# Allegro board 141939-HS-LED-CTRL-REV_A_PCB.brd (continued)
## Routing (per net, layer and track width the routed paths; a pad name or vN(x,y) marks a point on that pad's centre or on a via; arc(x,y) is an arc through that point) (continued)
GND_EARTH:
  vias: v1(4.96,54.2) v1(4.96,52.93) v1(4.96,51.66) v1(6.48,54.2)
VCC_5V: length 3.2
  TOP w0.381: v1(18.55,50.9) 18.55,48.99 19.02,48.52 R1.2
  vias: v1(18.55,53.44) v1(18.55,52.17) v1(19.82,53.44) v1(19.82,52.17) v1(24.77,50.01) v1(24.77,49.12) v1(25.66,50.01) v1(25.66,49.12) v1(26.67,50.01) v1(26.67,49.12)
VDDIO_A_RGMII: length 21
  TOP w0.178: U8.27 47.25,33.66 v1(47.41,33.5)
  TOP w0.381: R96.1 R103.1 v1(45.21,31.72) ; R91.1 v1(56.3,33.12)
  BOTTOM w0.381: v1(47.41,33.5) 46.99,33.91 46.99,34.42 47.34,34.77 C44.1 R120.1 ; v1(47.41,33.5) 46.45,33.5 45.21,32.26 v1(45.21,31.72) ; v1(47.41,33.5) 47.95,34.04 55.38,34.04 v1(56.3,33.12)
VDDIO_B_RGMII: length 27
  TOP w0.178: v1(47.41,15.97) 47.25,16.13 U9.27
  TOP w0.381: R98.1 R104.1 v1(46.14,13.46) 46.26,13.34 v1(47.88,13.34) ; R93.1 v1(56.81,16.61)
  BOTTOM w0.381: v1(46.14,13.46) 46.14,12.41 47.12,11.43 49.66,11.43 51.94,13.72 53.98,13.72 54.86,14.61 54.86,14.67 v1(56.81,16.61) ; R122.1 C46.1 47.63,17.11 47.63,16.19 v1(47.41,15.97) 47.78,15.97 48.26,15.49 48.26,13.72 v1(47.88,13.34)
AB16: length 33.1
  TOP w0.152: U26.58 106.85,12.27 105.44,10.87 101.15,10.87 97.1,14.92 85.41,14.92 83.82,16.51 83.82,17.65 83.28,18.19 82.87,18.19 82.41,18.65 82.41,19.57 82.41,19.57 P1.A10
AB17: length 35.6
  TOP w0.152: U26.59 107.35,12.07 105.8,10.51 101,10.51 97.06,14.45 85.22,14.45 81.89,17.78 81.89,21.68 P1.B11
AB18: length 35.9
  TOP w0.152: U26.60 107.85,11.95 106.03,10.13 96.06,10.13 93.01,13.18 85.77,13.18 81.41,17.54 P1.A11
AB19: length 34.3
  TOP w0.152: U26.2 114.85,26.17 111.76,23.08 105.54,23.08 v1(105.41,23.21) ; P1.F3 v1(88.91,25.66)
  BOTTOM w0.152: v1(105.41,23.21) 104.78,22.58 103.26,22.58 101.99,21.31 93.22,21.31 91.1,23.43 90.44,23.43 89.41,24.46 89.41,25.16 v1(88.91,25.66)
ARM_CLK: length 27.3
  TOP w0.152: v1(104.27,23.21) 104.91,23.85 108.72,23.85 109.85,24.98 U26.12 ; P1.D3 89.91,23.66 92.26,23.66 v1(92.71,23.21)
  BOTTOM w0.152: v1(92.71,23.21) 94.24,21.69 101.86,21.69 103.13,22.96 104.02,22.96 v1(104.27,23.21)
AS_DAT0: length 12.4
  TOP w0.152: R13.1 95.01,34.65 94.37,34.01 94.37,31.21 91.83,28.67 90.92,28.67 P1.H2
ASDO: length 22
  TOP w0.152: U7.5 104.15,33.12 101.79,30.77 101.79,29.24 100.46,27.91 100.46,24.48 99.06,23.08 96.4,23.08 95.89,22.58 92,22.58 P1.C1
CAN_RX: length 104.8
  TOP w0.152: v1(30.48,3.56) 30.61,3.68 41.43,3.68 43.59,1.52 104.91,1.52 107.7,4.32 107.7,7.72 112.85,12.87 U26.70
  BOTTOM w0.152: J6.5 20.44,4.19 29.84,4.19 v1(30.48,3.56)
CAN_TX: length 109.8
  TOP w0.152: v1(30.48,2.41) 42.16,2.41 43.43,1.14 105.06,1.14 108.21,4.29 108.21,7.59 113.35,12.73 U26.71
  BOTTOM w0.152: J6.4 18.95,4.7 30.35,4.7 31.11,3.94 31.11,3.05 v1(30.48,2.41)
CLK_25M: length 5.6
  TOP w0.152: X4.3 95.64,26.65 94.16,25.16 P1.E1
CONF_DONE: length 12.4
  TOP w0.152: v1(68.09,25.89) 68.6,25.89 69.76,27.05 74.33,27.05 74.76,27.48 76.03,27.48 76.2,27.66 77.73,27.66 78.24,28.16 P1.H14
  BOTTOM w0.152: R18.1 67.84,25.89 v1(68.09,25.89)
DB0: length 38.6
  TOP w0.152: P1.B12 80.89,21.68 80.89,17.51 85.6,12.8 92.84,12.8 95.9,9.74 106.35,9.74 108.35,11.74 U26.61
DB1: length 39
  TOP w0.152: P1.A12 80.41,17.23 85.22,12.42 92.46,12.42 95.64,9.24 106.56,9.24 108.85,11.53 U26.62
DB2: length 38.2
  TOP w0.152: U26.81 116.08,18.19 115.58,17.69 111.7,17.69 109.1,15.08 103,15.08 102.49,14.57 100.23,14.57 98.07,16.73 87.66,16.73 85.91,18.48 85.91,21.66 P1.B7
DB3: length 36.3
  TOP w0.152: U26.82 115.83,18.69 115.24,18.1 111.41,18.1 108.77,15.46 102.87,15.46 102.47,15.06 100.38,15.06 98.22,17.22 87.71,17.22 86.41,18.52 P1.A6
DB4: length 10.4
  TOP w0.152: U26.38 94.52,21.69 94.05,22.16 P1.B1
DB5: length 11.6
  TOP w0.152: U26.39 92.58,21.19 92.13,21.64 90.88,21.64 P1.A2
DB6: length 13.7
  TOP w0.152: U26.40 94.89,20.69 94.36,20.16 90.56,20.16 89.89,20.83 89.89,21.68 P1.B3
DB7: length 13.2
  TOP w0.152: U26.41 95.02,20.19 94.64,19.8 90.28,19.8 89.41,20.67 P1.A3
DB8: length 15
  TOP w0.152: P1.B4 88.89,21.68 88.89,20.69 90.16,19.42 94.76,19.42 95.03,19.69 U26.42
DB9: length 14.6
  TOP w0.152: P1.A4 88.41,20.4 89.79,19.02 95,19.02 95.17,19.19 U26.43
DB10: length 16.9
  TOP w0.152: P1.B5 87.91,21.66 87.91,19.63 88.9,18.64 100.46,18.64 100.51,18.69 U26.44
DB11: length 16.6
  TOP w0.152: P1.A5 87.41,19.12 88.34,18.19 U26.45
DB12: length 18.8
  TOP w0.152: P1.B6 86.91,21.66 86.91,18.73 87.95,17.69 U26.46
DB13: length 26.7
  TOP w0.152: U26.55 105.35,12.9 104.56,12.1 101.94,12.1 97.69,16.35 87.41,16.35 85.41,18.35 P1.A7
DB14: length 30.4
  TOP w0.152: U26.56 105.85,12.69 104.89,11.73 101.55,11.73 97.37,15.92 87.33,15.92 84.91,18.34 84.91,22.66 P1.C8
DB15: length 32.4
  TOP w0.152: U26.57 106.35,12.48 105.14,11.27 101.38,11.27 97.23,15.42 85.68,15.42 84.2,16.89 84.2,17.88 83.92,18.16 83.92,19.89 82.89,20.92 82.89,21.68 P1.B10
DCLK: length 18.6
  TOP w0.152: U7.6 104.53,34.39 102.62,32.48 99.06,32.48 98.39,33.15 95.25,33.15 94.82,32.72 94.82,31.16 91.82,28.16 P1.H1
ENET_AVDD_3.3: length 32
  TOP w0.178: v2(40.93,38.44) 41.95,38.44 42.17,38.67 U8.14 ; U9.14 40.58,21.14 v2(39.88,21.85)
  BOTTOM w0.381: v2(39.88,21.85) 39.88,26.13 40.14,26.39 40.14,32.13 39.79,32.48 39.79,37.05 40.93,38.2 v2(40.93,38.44) 40.79,38.58 40.68,38.58 39.41,39.85 C59.1 38.39,41.12 C60.1 38.42,42.04 FB3.2
ENET_DVDD_3.3: length 113.3
  TOP w0.178: v2(47.87,41.88) 47.65,41.65 U8.3 ; v2(47.87,24.35) 47.65,24.13 U9.3
  TOP w0.381: v1(42.17,23.97) 41.53,23.97 v1(40.64,24.86) ; R148.1 v1(14.1,12.54) ; R149.1 v1(17.53,12.54) ; R146.1 v1(17.15,48.99) ; R147.1 v1(14.1,48.99)
  BOTTOM w0.381: 15.15,48.99 15.15,47.85 16.29,46.71 28.1,46.71 28.87,47.47 39.15,47.47 40.04,46.58 R94.2 40.04,44.07 FB3.1 40.46,43.66 C58.1 ; 15.15,48.99 v1(17.15,48.99) ; 15.15,48.99 v1(14.1,48.99) ; C58.1 42.07,43.53 42.07,38.2 40.37,36.49 40.37,33.04 40.77,32.64 40.77,24.99 v1(40.64,24.86) 40.64,19.88 39.03,18.26 39.03,14.19 37.37,12.54 v1(17.53,12.54) v1(14.1,12.54) ; C58.1 45.25,43.66 46.26,42.64 C57.1 47.03,42.39 47.53,41.88 v2(47.87,41.88) ; v2(47.87,24.35) 47.11,25.12 44.96,25.12 44.71,24.86 43.06,24.86 v1(42.17,23.97)
ENETA_AVDD_1.1: length 21.7
  TOP w0.178: v2(42.84,37.18) 43.11,37.18 43.4,37.47 U8.17 ; v2(46.29,42.01) 46.45,41.85 U8.6 ; U8.11 43.72,39.87 43.47,40.12 v2(43.47,40.53)
  TOP w0.381: FB1.2 v1(48.8,46.58)
  BOTTOM w0.381: C51.1 43.34,36.67 v2(42.84,37.18) 43.6,37.94 C48.1 43.6,40.38 43.47,40.51 ; 43.47,40.51 44.21,41.24 C47.1 ; 43.47,40.51 v2(43.47,40.53) ; v2(46.29,42.01) 46.39,41.91 C47.1 ; C47.1 48.17,41.24 48.8,41.88 v1(48.8,46.58)
ENETA_DVDD_1.1: length 10.3
  TOP w0.178: v1(50.2,39.34) 49.93,39.07 U8.38
  TOP w0.381: FB1.1 C50.1 C49.1 51.6,43.02 L6.1 50.62,42.04 v1(50.2,41.63)
  BOTTOM w0.381: v1(50.2,41.63) v1(50.2,39.34)
ENETA_DVDD_2.5: length 61.9
  TOP w0.178: U8.8 45.65,41.3 45.25,41.7 v2(45.25,41.88)
  TOP w0.381: R125.1 v1(41.06,35.1) ; R124.1 v1(54.14,40.61) ; v1(42.2,29.48) 42.63,29.48 42.96,29.81 R100.1 ; R123.1 v1(54.14,39.34) ; R126.1 v1(54.14,41.88)
  BOTTOM w0.381: v1(54.14,41.88) v1(54.14,40.61) v1(54.14,39.34) ; v1(54.14,39.34) 54.14,39.09 52.36,37.31 C43.1 48.8,35.83 R120.2 ; v1(54.14,39.34) 55.5,37.98 55.5,35.56 56.39,34.67 58.04,34.67 59.18,33.53 59.18,32 56.77,29.59 50.29,29.59 49.02,30.86 46.48,30.86 45.97,30.35 43.69,30.35 42.82,29.48 v1(42.2,29.48) 41.48,30.21 41.48,34.09 41.06,34.51 v1(41.06,35.1) 41.06,36.29 42.71,37.94 42.71,40.86 43.72,41.88 v2(45.25,41.88)
ENETA_GTX_CLK: length 24.2
  TOP w0.152: R39.1 56.68,35.4 57.47,34.61 62.07,34.61 62.38,34.92 62.68,34.92 62.99,34.61 63.28,34.61 63.88,34.01 71.71,34.01 v1(71.84,33.88) ; P1.P14 v1(77.91,33.66)
  BOTTOM w0.152: v1(77.91,33.66) 77.72,33.85 71.86,33.85 v1(71.84,33.88)
ENETA_INTN: length 46
  TOP w0.152: v1(79.91,30.66) 80.41,30.16 P1.K12 ; R125.2 43.8,35.1 v2(43.85,35.15) 43.85,36.14 43.98,36.27 U8.20 ; v1(58.17,33.53) 58.17,33.58 58.37,33.78 62.87,33.78 63.66,32.99 71.05,32.99 71.28,32.77 v1(71.28,32.2)
  BOTTOM w0.152: v1(79.91,30.66) 79.41,31.16 78.69,31.16 78.49,31.37 78.49,31.38 78.41,31.46 78.41,31.95 77.98,32.38 73.53,32.38 73.46,32.46 73.46,32.46 73.13,32.79 72.54,32.79 71.96,32.2 v1(71.28,32.2) ; v2(43.85,35.15) 43.85,34.48 44.32,34.01 44.32,31.75 44.96,31.11 45.97,31.11 46.48,31.62 56.26,31.62 v1(58.17,33.53)
ENETA_LED_1000: length 7.2
  TOP w0.152: R56.1 R100.2 R76.2 44.3,31.51 44.3,34.2 44.74,34.64 44.87,34.64 45.25,35.02 U8.22
ENETA_LED_ACT: length 4.5
  TOP w0.152: R51.1 R90.2 R73.2 44.49,35.02 44.49,35.02 44.84,35.38 U8.21
ENETA_MDC: length 30.7
  TOP w0.152: U8.40 49.33,39.87 50.07,40.61 R124.2 52.23,41.12 52.36,41.24 55.03,41.24 58.93,37.34 72.36,37.34 74.54,35.16 P1.R16
ENETA_MDI_N0: length 9.8
  TOP w0.13: U8.10 44.84,40.86 44.88,40.9 44.88,41.02 44.6,41.29 43.07,41.29 42.92,41.14 42.92,41.02 42.77,40.86 42.55,40.86 42.4,41.02 42.4,41.14 42.25,41.29 40.57,41.29 39.84,40.57 38.14,40.57 37.8,40.23 U23.23
ENETA_MDI_N1: length 8.3
  TOP w0.13: U23.20 37.8,37.18 38.14,37.52 38.48,37.52 40.06,39.1 43.53,39.1 43.56,39.07 U8.13
ENETA_MDI_N2: length 9.4
  TOP w0.13: U23.17 37.76,34.13 38.1,34.47 38.57,34.47 39.03,34.93 39.03,35.53 40.93,37.43 42.29,37.43 42.76,37.9 43.82,37.9 43.85,37.87 U8.16
ENETA_MDI_N3: length 11.1
  TOP w0.13: U23.14 37.8,31.08 38.14,31.43 38.48,31.43 40.3,33.24 40.3,35.31 41.27,36.29 43.24,36.29 43.65,36.7 43.82,36.7 43.85,36.67 U8.19
ENETA_MDI_P0: length 9.8
  TOP w0.13: U23.24 37.8,41.24 38.14,40.9 39.7,40.9 40.43,41.63 44.74,41.63 45.21,41.15 45.21,40.9 45.25,40.86 U8.9
ENETA_MDI_P1: length 8.3
  TOP w0.13: U23.21 37.8,38.2 38.14,37.86 38.34,37.86 39.92,39.44 43.53,39.44 43.56,39.47 U8.12
ENETA_MDI_P2: length 9.4
  TOP w0.13: U8.15 43.85,38.27 43.82,38.24 42.62,38.24 42.15,37.77 40.79,37.77 38.69,35.67 38.69,35.07 38.43,34.81 38.1,34.81 37.76,35.15 U23.18
ENETA_MDI_P3: length 11.1
  TOP w0.13: U23.15 37.8,32.1 38.14,31.76 38.34,31.76 39.96,33.38 39.96,35.45 41.14,36.62 43.1,36.62 43.52,37.04 43.85,37.04 43.88,37.07 U8.18
ENETA_MDIO: length 31.7
  TOP w0.152: P1.P15 76.93,34.64 74.43,34.64 72.11,36.96 58.43,36.96 55.41,39.97 52.49,39.97 52.23,39.72 R123.2 51.6,39.34 50.96,39.97 50.02,39.97 49.52,39.47 U8.39
ENETA_RESETN: length 32.9
  TOP w0.152: U8.1 48.45,40.76 48.68,40.99 50.96,40.99 51.85,41.88 R126.2 52.23,42.39 52.36,42.51 54.32,42.51 59.11,37.72 72.74,37.72 73.28,37.18 76.39,37.18 P1.T15
ENETA_RX_CLK: length 35.6
  TOP w0.152: P1.M15 77.41,31.85 77.21,31.64 76.15,31.64 75.54,32.26 73.79,32.26 73.2,31.67 72.44,31.67 72.26,31.85 72.26,32.4 72.15,32.51 71.99,32.51 71.88,32.4 71.88,31.83 71.68,31.62 70.82,31.62 70.61,31.83 70.61,32.35 70.45,32.51 70.22,32.51 70.06,32.35 70.06,31.8 69.88,31.62 69.62,31.62 69.45,31.8 69.45,32.33 69.27,32.51 69.02,32.51 68.84,32.33 68.84,31.8 68.66,31.62 68.41,31.62 68.23,31.8 68.23,32.35 68.07,32.51 67.85,32.51 67.69,32.35 67.69,31.8 67.51,31.62 67.26,31.62 67.08,31.8 67.08,32.43 66.9,32.61 66.65,32.61 66.47,32.43 66.47,31.93 66.29,31.75 66.04,31.75 65.86,31.93 65.86,32.43 65.68,32.61 63.96,32.61 63.75,32.41 63.75,32.28 63.61,32.13 63.39,32.13 63.25,32.28 63.25,32.87 63.1,33.02 62.89,33.02 62.74,32.87 62.74,32.02 62.59,31.88 62.38,31.88 62.24,32.02 62.24,33.1 62.06,33.27 58.75,33.27 58.55,33.07 58.55,32.97 58.34,32.77 56.98,32.77 56.69,32.48 54.55,32.48 54.35,32.68 R121.1
ENETA_RX_D0: length 33.2
  TOP w0.152: P1.L15 76.92,30.68 76.1,30.68 75.57,31.21 73.79,31.21 73.52,30.95 72.98,30.95 72.78,30.75 65.91,30.75 65.66,31.01 63.37,31.01 63.35,30.99 63.23,30.99 63.05,30.81 63.05,30.4 62.87,30.23 62.62,30.23 62.44,30.4 62.44,30.81 62.26,30.99 62.01,30.99 61.83,30.81 61.83,30.4 61.65,30.23 61.4,30.23 61.22,30.4 61.22,30.8 61.04,30.99 60.78,30.99 60.59,30.8 60.59,30.11 60.3,29.81 60.09,29.81 59.91,29.99 59.91,30.81 59.73,30.99 59.48,30.99 59.3,30.81 59.3,29.99 59.12,29.81 58.87,29.81 58.69,29.99 58.69,30.81 58.51,30.99 58.26,30.99 58.08,30.81 58.08,29.99 57.9,29.81 57.65,29.81 57.47,29.99 57.47,30.81 57.29,30.99 57.04,30.99 56.86,30.81 56.86,29.99 56.68,29.81 54.48,29.81 54.35,29.95 R27.1
ENETA_RX_D1: length 34.5
  TOP w0.152: v1(73.54,30.39) 73.43,30.28 65.86,30.28 65.51,30.63 63.88,30.63 63.62,30.36 63.62,29.96 63.5,29.84 60.83,29.84 60.42,29.43 60.1,29.43 59.92,29.26 59.92,29.01 59.75,28.83 59.49,28.83 59.31,29.01 59.31,29.26 59.14,29.43 58.88,29.43 58.7,29.26 58.7,29.01 58.53,28.83 58.27,28.83 58.1,29.01 58.1,29.26 57.92,29.43 57.66,29.43 57.49,29.26 57.49,29.01 57.31,28.83 57.05,28.83 56.88,29.01 56.88,29.26 56.7,29.43 56.45,29.43 56.27,29.26 56.27,29.01 56.1,28.83 55.84,28.83 55.66,29.01 55.66,29.26 55.49,29.43 55.23,29.43 55.06,29.26 55.06,29.01 54.88,28.83 54.62,28.83 54.45,29.01 54.45,29.26 54.27,29.43 53.47,29.43 53,29.91 R30.1 ; P1.J12 80.41,29.16 v1(79.91,29.66)
  BOTTOM w0.152: v1(79.91,29.66) 79.41,30.16 78.61,30.16 78.38,30.39 78.38,30.96 78.18,31.16 74.31,31.16 v1(73.54,30.39)
ENETA_RX_D2: length 34.9
  TOP w0.152: v1(73.54,29.26) 72.9,29.89 68.16,29.89 67.49,29.23 63.81,29.23 63.58,29 63.58,28.66 63.34,28.42 63.04,28.42 62.86,28.6 62.86,29.29 62.68,29.46 62.43,29.46 62.25,29.29 62.25,28.6 62.07,28.42 61.82,28.42 61.64,28.6 61.64,29.29 61.46,29.46 61.21,29.46 61.03,29.29 61.03,28.6 60.85,28.42 53.88,28.42 52.61,29.69 50.58,29.69 R35.1 ; v1(77.91,29.66) 78.41,29.16 P1.J14
  BOTTOM w0.152: v1(77.91,29.66) 74.37,29.66 73.96,29.26 v1(73.54,29.26)
ENETA_RX_D3: length 39
  TOP w0.152: v1(78.91,29.66) 79.41,29.16 P1.J13 ; R37.1 44.65,32.52 44.65,31.43 45.47,30.61 48.52,30.61 49.06,30.07 49.62,30.07 50.51,29.18 52.48,29.18 53.62,28.04 67.31,28.04 68.54,29.26 v1(72.65,29.26)
  BOTTOM w0.152: v1(78.91,29.66) 78.67,29.66 78.17,30.16 74.28,30.16 73.94,29.82 73.21,29.82 v1(72.65,29.26)
ENETA_RX_DV: length 36.2
  TOP w0.152: P1.L16 76.13,31.16 75.57,31.72 73.76,31.72 73.34,31.3 72.61,31.3 72.52,31.21 65.99,31.21 65.79,31.41 62.01,31.41 61.83,31.59 61.83,32.71 61.65,32.89 61.4,32.89 61.22,32.71 61.22,31.54 61.05,31.37 60.8,31.37 60.62,31.54 60.62,32.71 60.44,32.89 60.19,32.89 60.01,32.71 60.01,31.51 59.87,31.37 59.67,31.37 59.53,31.51 59.53,32.71 59.35,32.89 59.09,32.89 58.92,32.71 58.92,31.52 58.77,31.37 58.56,31.37 58.41,31.52 58.41,32.21 58.23,32.38 57.98,32.38 57.8,32.21 57.8,31.55 57.62,31.37 57.37,31.37 57.19,31.55 57.19,31.83 57.01,32 56.76,32 56.58,31.83 56.58,31.28 56.41,31.11 56.18,31.11 56.01,31.28 56.01,31.88 55.78,32.1 53.92,32.1 53.72,32.3 53.72,33.02 53.62,33.12 R24.1
ENETA_TX_D0: length 27.3
  TOP w0.152: P1.N14 77.88,32.63 73.89,32.63 72.01,34.51 64.52,34.51 64.34,34.69 64.34,34.83 63.86,35.31 57.28,35.31 56.55,36.04 54.01,36.04 53.38,36.67 R43.1
ENETA_TX_D1: length 24.4
  TOP w0.152: R45.1 56.68,36.67 57.67,35.68 64.64,35.68 64.82,35.5 64.82,35.2 65,35.02 65.25,35.02 65.43,35.2 65.43,35.5 65.61,35.68 65.86,35.68 66.04,35.5 66.04,35.2 66.22,35.02 66.47,35.02 66.65,35.2 66.65,35.5 66.83,35.68 67.08,35.68 67.26,35.5 67.26,35.2 67.44,35.02 72.14,35.02 74,33.16 P1.N16
ENETA_TX_D2: length 27.4
  TOP w0.152: R47.1 53.38,37.69 53.63,37.69 54.01,37.31 56.81,37.31 57.92,36.2 67.61,36.2 67.79,36.02 67.79,35.71 67.97,35.53 68.22,35.53 68.4,35.71 68.4,36.02 68.58,36.2 68.83,36.2 69.01,36.02 69.01,35.71 69.19,35.53 72.27,35.53 74.17,33.62 76.95,33.62 P1.N15
ENETA_TX_D3: length 24.5
  TOP w0.152: R49.1 56.68,37.94 58.04,36.58 69.37,36.58 69.54,36.4 69.54,36.06 69.72,35.89 69.97,35.89 70.15,36.06 70.15,36.4 70.33,36.58 70.58,36.58 70.76,36.4 70.76,36.06 70.94,35.89 71.19,35.89 71.37,36.06 71.37,36.4 71.55,36.58 71.86,36.58 74.27,34.16 P1.P16
ENETA_TX_EN: length 27.1
  TOP w0.152: v1(77.91,31.66) 78.41,31.16 P1.L14 ; R41.1 53.4,35.4 54.04,34.77 56.68,34.77 57.28,34.16 63,34.16 63.66,33.5 71.4,33.5 71.63,33.27 72.01,33.27 72.9,32.38 v1(72.9,32.23)
  BOTTOM w0.152: v1(72.9,32.23) 73.47,31.66 v1(77.91,31.66)
ENETB_AVDD_1.1: length 23.5
  TOP w0.178: v2(42.84,22.58) 43.07,22.34 U9.11 ; U9.6 46.45,24.33 v2(46.29,24.48) ; v2(42.84,19.65) 43.11,19.65 43.4,19.94 U9.17
  TOP w0.381: FB2.2 49.95,28.93 v1(49.57,29.31)
  BOTTOM w0.381: v2(46.29,24.48) 46.39,24.38 C54.1 ; C56.1 43.09,22.32 v2(42.84,22.58) ; C56.1 43.6,22.96 43.85,23.21 45.12,23.21 45.63,23.72 C54.1 ; C56.1 43.6,20.42 v2(42.84,19.65) 43.34,19.15 C55.1 ; C54.1 48.39,23.72 49.57,24.89 v1(49.57,29.31)
ENETB_DVDD_1.1: length 10.9
  TOP w0.178: v1(50.2,21.81) 49.93,21.54 U9.38
  TOP w0.381: FB2.1 52.74,27.91 C53.1 C52.1 53,25.75 L7.1 51.51,24.77 50.96,24.23 v1(50.58,24.23)
  BOTTOM w0.381: v1(50.58,24.23) 50.2,23.85 v1(50.2,21.81)
ENETB_DVDD_2.5: length 45.2
  TOP w0.178: U9.8 45.65,23.78 45.25,24.18 v2(45.25,24.35)
  TOP w0.381: R29.1 v1(40.93,17.5) ; R23.1 v1(53.43,21.81) ; R34.1 v1(54.82,24.35) ; R26.1 v1(53.43,23.08) ; R102.1 v1(41.01,14.83)
  BOTTOM w0.381: v1(54.82,24.35) 54.14,24.35 53.43,23.64 v1(53.43,23.08) v1(53.43,21.81) 51.39,19.78 C45.1 48.8,18.3 R122.2 49.28,18.26 49.66,17.88 49.66,12.83 49.4,12.57 47.37,12.57 46.91,13.03 46.91,13.79 45.88,14.83 v1(41.01,14.83) 40.3,15.54 40.3,16.86 v1(40.93,17.5) 40.93,18.26 42.21,19.54 42.21,22.97 43.34,24.1 44.99,24.1 v2(45.25,24.35)
ENETB_GTX_CLK: length 29.1
  TOP w0.152: R40.1 53.63,18.89 54.14,19.4 56.77,19.4 57.95,20.57 59.18,20.57 61.69,23.08 69.1,23.08 70.11,24.1 75.03,24.1 75.57,24.63 76.61,24.63 76.92,24.94 76.92,25.45 77.12,25.65 77.9,25.65 P1.F14
ENETB_INTN: length 53
  TOP w0.152: R29.2 43.68,17.5 v1(43.7,17.52) 43.7,18.47 43.98,18.74 U9.20 ; v1(76.84,17.75) 76.84,15.63 75.56,14.35 59.98,14.35 57.54,11.91 45.22,11.91 44.2,12.92 v1(44.2,15.59) ; P1.C11 v1(80.91,22.66)
  BOTTOM w0.152: v1(44.2,15.59) 44.2,17.02 v1(43.7,17.52) ; v1(76.84,17.75) 77.22,18.13 77.22,20.29 77.47,20.54 80.4,20.54 80.91,21.05 v1(80.91,22.66)
ENETB_LED_1000: length 6
  TOP w0.152: R60.1 R102.2 R89.2 43.47,15.97 44.61,17.11 44.87,17.11 45.25,17.49 U9.22
ENETB_LED_ACT: length 8
  TOP w0.152: R52.1 R92.2 R77.2 40.8,16.61 43.6,16.61 44.49,17.5 44.49,17.5 44.84,17.85 U9.21
ENETB_MDC: length 31.8
  TOP w0.152: U9.40 49.33,22.34 50.07,23.08 R26.2 51.6,23.46 51.85,23.72 55.41,23.72 58.61,26.92 64.55,26.92 64.9,27.27 68.3,27.27 69.22,28.19 73.95,28.19 75.44,29.69 76.93,29.69 P1.K15
ENETB_MDI_N0: length 11.6
  TOP w0.13: U23.11 37.8,28.04 38.14,28.38 38.97,28.38 41.2,26.15 41.2,25.74 43.22,23.72 43.55,23.72 43.7,23.57 43.7,23.45 43.85,23.3 44.06,23.3 44.22,23.45 44.22,23.57 44.37,23.72 44.65,23.72 44.88,23.49 44.88,23.34 44.84,23.3 U9.10
ENETB_MDI_N1: length 9.2
  TOP w0.13: U9.13 43.56,21.54 43.53,21.58 42.31,21.58 38.56,25.33 38.14,25.33 37.8,24.99 U23.8
ENETB_MDI_N2: length 8.5
  TOP w0.13: U23.5 37.29,21.94 37.63,22.28 37.92,22.28 39.83,20.38 43.53,20.38 43.56,20.34 U9.16
ENETB_MDI_N3: length 8
  TOP w0.13: U23.2 37.8,18.89 38.14,19.23 38.47,19.23 38.94,18.77 43.23,18.77 43.64,19.18 43.85,19.18 43.88,19.14 U9.19
ENETB_MDI_P0: length 11.7
  TOP w0.13: U23.12 37.8,29.05 38.14,28.71 39.11,28.71 41.53,26.29 41.53,25.88 43.36,24.05 44.79,24.05 45.21,23.63 45.21,23.34 45.25,23.3 U9.9
ENETB_MDI_P1: length 9.2
  TOP w0.13: U9.12 43.56,21.94 43.53,21.91 42.45,21.91 38.69,25.66 38.14,25.66 37.8,26 U23.9
ENETB_MDI_P2: length 8.5
  TOP w0.13: U23.6 37.29,22.96 37.63,22.62 38.06,22.62 39.96,20.71 43.53,20.71 43.56,20.74 U9.15
ENETB_MDI_P3: length 8
  TOP w0.13: U9.18 43.88,19.54 43.85,19.51 43.5,19.51 43.09,19.1 39.07,19.1 38.6,19.57 38.14,19.57 37.8,19.91 U23.3
ENETB_MDIO: length 31.1
  TOP w0.152: P1.J16 75.43,29.16 74.08,27.81 69.38,27.81 68.48,26.92 65.18,26.92 64.68,26.42 58.61,26.42 55.54,23.34 54.49,23.34 53.6,22.45 51.73,22.45 51.6,22.32 R23.2 51.09,21.81 50.53,22.37 49.92,22.37 49.49,21.94 U9.39
ENETB_RESETN: length 31.3
  TOP w0.152: P1.K16 75.41,30.16 73.82,28.57 68.88,28.57 67.96,27.66 64.77,27.66 64.55,27.43 58.49,27.43 56.04,24.99 53.38,24.99 53,24.61 R34.2 51.85,24.35 51.09,23.59 48.8,23.59 48.45,23.23 U9.1
ENETB_RX_CLK: length 34.6
  TOP w0.152: R22.1 57.33,17.71 57.66,18.03 57.66,18.73 57.85,18.92 58.13,18.92 58.32,18.73 58.32,17.96 58.5,17.78 58.75,17.78 58.93,17.96 58.93,19 59.11,19.18 59.36,19.18 59.54,19 59.54,17.96 59.72,17.78 59.97,17.78 60.15,17.96 60.15,19 60.33,19.18 60.58,19.18 60.76,19 60.76,17.96 60.94,17.78 61.19,17.78 61.37,17.96 61.37,19 61.55,19.18 61.8,19.18 61.98,19 61.98,17.96 62.16,17.78 62.41,17.78 62.59,17.96 62.59,19 62.77,19.18 68.23,19.18 72.01,22.96 75.06,22.96 75.8,23.69 76.69,23.69 76.93,23.94 76.93,24.44 77.41,24.92 P1.E15
ENETB_RX_D0: length 32.4
  TOP w0.152: R28.1 57.12,15.34 58.55,16.76 68.2,16.76 70.02,18.58 70.27,18.58 70.84,18 71.1,18 71.27,18.18 71.27,18.44 70.7,19.01 70.7,19.26 70.88,19.44 71.13,19.44 71.71,18.87 71.96,18.87 72.14,19.05 72.14,19.3 71.56,19.87 71.56,20.13 71.74,20.31 71.99,20.31 72.57,19.73 72.82,19.73 73,19.91 73,20.16 72.42,20.74 72.42,20.99 72.6,21.17 72.86,21.17 73.43,20.59 73.68,20.59 73.86,20.77 73.86,21.02 73.29,21.6 73.29,21.85 73.5,22.07 75.32,22.07 75.92,22.68 76.69,22.68 77.17,23.16 P1.C15
ENETB_RX_D1: length 33.4
  TOP w0.152: R32.1 52.87,13.43 56.93,13.43 57.76,14.26 57.76,14.51 57.53,14.73 57.53,14.99 57.71,15.16 57.96,15.16 58.19,14.94 58.44,14.94 58.62,15.12 58.62,15.37 58.39,15.6 58.39,15.85 58.57,16.03 58.83,16.03 59.05,15.8 59.3,15.8 59.76,16.26 69.85,16.26 70.21,16.61 70.46,16.61 70.83,16.24 71.08,16.24 71.26,16.42 71.26,16.67 70.89,17.04 70.89,17.3 71.07,17.48 71.32,17.48 71.69,17.1 71.95,17.1 72.13,17.28 72.13,17.53 71.75,17.91 71.75,18.16 71.93,18.34 72.18,18.34 72.56,17.97 72.81,17.97 72.99,18.14 72.99,18.4 72.62,18.77 72.62,19.02 75.03,21.43 75.32,21.43 76.05,22.16 P1.B16
ENETB_RX_D2: length 34.5
  TOP w0.152: P1.C14 77.92,22.68 77.19,22.68 76.89,22.37 76.89,21.86 76.71,21.69 76.2,21.69 75.32,20.8 75.03,20.8 73.6,19.37 73.6,18.22 70.99,15.62 59.85,15.62 57.15,12.92 49.82,12.92 R36.1
ENETB_RX_D3: length 38.4
  TOP w0.152: P1.A15 76.46,20.21 76.46,20.04 71.54,15.11 60.11,15.11 57.41,12.42 46.14,12.42 44.99,13.56 R38.1
ENETB_RX_DV: length 36.3
  TOP w0.152: P1.C16 75.78,23.16 75.19,22.58 73.12,22.58 67.94,17.4 67.64,17.4 67.46,17.58 67.46,18.62 67.28,18.8 67.03,18.8 66.85,18.62 66.85,17.58 66.67,17.4 66.42,17.4 66.24,17.58 66.24,18.62 66.06,18.8 65.81,18.8 65.63,18.62 65.63,17.58 65.45,17.4 65.2,17.4 65.02,17.58 65.02,18.62 64.84,18.8 64.59,18.8 64.41,18.62 64.41,17.58 64.24,17.4 63.98,17.4 63.8,17.58 63.8,18.62 63.63,18.8 63.37,18.8 63.19,18.62 63.19,17.58 63.02,17.4 58.58,17.4 57.15,15.97 53.88,15.97 53.76,16.1 R25.1
ENETB_TX_D0: length 26
  TOP w0.152: R44.1 56.52,20.04 58.09,21.61 58.34,21.61 58.58,21.37 58.83,21.37 59.01,21.55 59.01,21.8 58.77,22.04 58.77,22.29 58.95,22.47 59.21,22.47 59.44,22.23 59.7,22.23 59.87,22.41 59.87,22.66 59.64,22.9 59.64,23.15 60.05,23.57 68.86,23.57 70.41,25.12 74.68,25.12 75.26,25.7 76.66,25.7 77.12,26.16 P1.F15
ENETB_TX_D1: length 29.2
  TOP w0.152: R46.1 53.76,20.16 54.27,20.67 56.42,20.67 59.7,23.95 59.94,23.95 60.12,24.13 60.12,24.46 60.3,24.64 60.55,24.64 60.73,24.46 60.73,24.13 60.9,23.95 61.16,23.95 61.34,24.13 61.34,24.46 61.51,24.64 61.77,24.64 61.95,24.46 61.95,24.13 62.12,23.95 62.38,23.95 62.55,24.13 62.55,24.46 62.73,24.64 62.99,24.64 63.16,24.46 63.16,24.13 63.34,23.95 68.52,23.95 70.2,25.63 74.56,25.63 75.09,26.16 P1.F16
ENETB_TX_D2: length 25.3
  TOP w0.152: R48.1 56.61,22.02 56.86,22.02 56.9,21.98 57.15,21.98 57.33,22.15 57.33,22.41 57.29,22.45 57.29,22.7 57.47,22.88 57.72,22.88 57.76,22.84 58.02,22.84 58.2,23.02 58.2,23.27 58.15,23.31 58.15,23.57 59.6,25.02 64.33,25.02 65.02,24.33 68.3,24.33 70.15,26.17 74.46,26.17 74.93,26.64 76.89,26.64 P1.G15
ENETB_TX_D3: length 24.7
  TOP w0.152: P1.G16 74.95,27.16 74.43,26.64 69.98,26.64 68.05,24.71 65.46,24.71 64.52,25.65 58.84,25.65 58.14,24.95 58.14,24.7 58.31,24.53 58.31,24.27 58.13,24.1 57.88,24.1 57.71,24.27 57.45,24.27 57.28,24.09 57.28,23.84 57.45,23.66 57.45,23.41 57.27,23.23 57.02,23.23 56.84,23.4 56.59,23.4 R50.1
ENETB_TX_EN: length 25.1
  TOP w0.152: P1.D16 75.57,24.16 75,23.59 70.24,23.59 69.35,22.7 63.47,22.7 62.34,21.58 62.09,21.58 61.77,21.89 61.52,21.89 61.34,21.72 61.34,21.46 61.66,21.14 61.66,20.89 61.48,20.71 61.23,20.71 60.91,21.03 60.66,21.03 60.48,20.85 60.48,20.6 60.8,20.28 60.8,20.03 60.43,19.67 58.06,19.67 57.2,18.81 R42.1
F_CLK: length 39.4
  TOP w0.152: v1(105.41,18.51) 113.42,18.51 114.59,19.69 U26.84 ; P1.F8 v1(84.91,25.66)
  BOTTOM w0.152: v1(84.91,25.66) 85.41,25.16 85.41,22.27 85.98,21.69 85.98,20.19 88.22,17.95 104.86,17.95 v1(105.41,18.51)
F_NAD: length 33.5
  TOP w0.152: v1(104.27,20.8) 104.83,21.36 112.45,21.36 115.28,24.19 U26.93 ; P1.C3 v1(88.91,23.66)
  BOTTOM w0.152: v1(104.27,20.8) 103.38,20.8 102.75,20.16 89.79,20.16 89.41,20.55 P1.C3 v1(88.91,23.66)
F_NBL0: length 35.2
  TOP w0.152: v1(105.41,21.94) 111.96,21.94 116.21,26.19 U26.97 ; P1.E6 v1(86.91,24.66)
  BOTTOM w0.152: v1(105.41,21.94) 104.86,21.38 103.33,21.38 102.49,20.54 92.32,20.54 90.41,22.46 90.41,22.87 89.12,24.16 87.7,24.16 87.2,24.66 v1(86.91,24.66)
F_NBL1: length 30
  TOP w0.152: P1.C2 v1(90.91,22.66) ; v1(104.27,21.94) 104.83,22.5 111.94,22.5 116.13,26.69 U26.98
  BOTTOM w0.152: v1(104.27,21.94) 103.13,21.94 102.11,20.92 92.65,20.92 v1(90.91,22.66)
F_NCE2: length 33.6
  TOP w0.152: P1.D5 v1(87.91,23.66) ; v1(105.41,20.8) 112.87,20.8 113.76,21.69 U26.88
  BOTTOM w0.152: v1(87.91,23.66) 88.41,23.16 88.41,20.91 89.54,19.78 103,19.78 103.46,20.24 104.86,20.24 v1(105.41,20.8)
F_NWAIT: length 36.5
  TOP w0.152: P1.E7 v1(85.91,24.66) ; v1(104.27,19.65) 104.83,20.21 113,20.21 113.97,21.19 U26.87
  BOTTOM w0.152: v1(85.91,24.66) 86.41,24.16 87.12,24.16 87.41,23.87 87.41,21.15 89.23,19.32 103.26,19.32 103.59,19.65 v1(104.27,19.65)
GPIO: length 32
  TOP w0.152: v1(108.59,27.66) 108.35,27.89 U26.15 ; v1(87.91,28.66) 87.2,28.66 86.88,28.98 86.88,29.68 86.41,30.15 P1.K6
  BOTTOM w0.152: v1(87.91,28.66) 88.41,29.16 89.22,29.16 89.74,29.69 92.46,29.69 93.34,28.8 93.34,26.52 95.76,24.1 100.08,24.1 101.22,25.24 101.22,27.15 101.99,27.91 108.34,27.91 v1(108.59,27.66)
HUB1_A: length 29.6
  TOP w0.152: U29.8 v1(75.32,45.05) ; P1.T6 86.41,37.73 89.76,41.08 U28.7 89.76,45.09 88.27,46.58 75.82,46.58 v1(75.44,46.96)
  BOTTOM w0.152: v1(75.32,45.05) 75.32,46.84 v1(75.44,46.96)
HUB1_B: length 33.7
  TOP w0.152: v1(74.02,46.96) 74.66,47.59 76.71,47.59 77.35,46.96 88.9,46.96 90.41,45.45 U28.8 90.41,40.97 86.91,37.47 86.91,35.66 P1.R6 ; U29.6 v1(74.02,45.05)
  BOTTOM w0.152: v1(74.02,46.96) v1(74.02,45.05)
HUB1_B1: length 32.4
  TOP w0.152: v1(98.94,46.32) 98.94,46.2 97,44.26 U27.5 97,41.59 95.13,39.72 93.48,39.72 91.7,37.94 91.7,37.45 P1.T2 ; v1(95.89,47.09) 96.52,47.72 104.02,47.72 105.67,49.37 108.46,49.37 R160.1
  BOTTOM w0.152: v1(98.94,46.32) 96.65,46.32 v1(95.89,47.09)
HUB1_B2: length 30.9
  TOP w0.152: R163.1 107.57,41.88 102.87,46.58 100.21,46.58 v1(99.95,46.32) ; P1.R4 88.9,35.66 88.9,36.55 89.92,37.56 89.92,38.32 92.97,41.37 94.62,41.37 95.05,41.8 U27.2 95.05,44.6 97.03,46.58 v1(97.03,47.09)
  BOTTOM w0.152: v1(97.03,47.09) 97.16,46.96 99.32,46.96 v1(99.95,46.32)
HUB1_BUF_A: length 8.9
  TOP w0.152: J8.9 91.44,55.48 91.44,53.31 90.41,52.28 U28.13
HUB1_BUF_B: length 6.1
  TOP w0.152: U28.12 91.06,51.66 92.73,53.33 J8.10
HUB1_BUF_B1: length 9.1
  TOP w0.152: J8.3 99.06,55.48 99.06,53.56 97.65,52.15 U27.15
HUB1_BUF_B2: length 9.2
  TOP w0.152: J8.7 93.98,55.48 93.98,53.56 95.7,51.85 U27.18
HUB1_BUF_C: length 8.6
  TOP w0.152: U28.15 89.11,51.23 88.9,51.43 88.9,55.48 J8.11
HUB1_BUF_CLK: length 9
  TOP w0.152: J8.13 86.49,55.61 86.49,51.23 87.81,49.91 U28.17
HUB1_BUF_D: length 5.6
  TOP w0.152: J8.12 89.76,53.8 U28.14
HUB1_BUF_G1: length 7
  TOP w0.152: U27.13 98.95,50.29 J8.2
HUB1_BUF_G2: length 5.7
  TOP w0.152: U27.16 97,52.39 97.81,53.2 J8.6
HUB1_BUF_LATCH: length 5.7
  TOP w0.152: U28.16 88.46,53.42 J8.14
HUB1_BUF_OE: length 9.9
  TOP w0.152: U28.18 87.16,49.8 83.82,53.13 83.82,55.48 J8.15
HUB1_BUF_R1: length 9.8
  TOP w0.152: J8.1 101.48,55.36 101.48,53.56 98.3,50.39 U27.14
HUB1_BUF_R2: length 8.5
  TOP w0.152: U27.17 96.35,52.93 96.52,53.1 96.52,55.48 J8.5
HUB1_C: length 26.9
  TOP w0.152: P1.T7 85.41,38 88.46,41.05 U28.5 88.46,44.86 87.51,45.82 75.19,45.82 74.67,45.3 U29.7
HUB1_CLK: length 29.9
  TOP w0.152: U29.5 73.37,41.54 73.79,41.12 76.46,41.12 77.09,41.75 77.09,44.67 77.47,45.05 86.36,45.05 87.16,44.26 U28.3 87.16,41.15 82.94,36.93 82.94,35.69 P1.R10
HUB1_D: length 30.7
  TOP w0.152: P1.R7 85.91,35.66 85.91,37.87 89.11,41.07 U28.6 89.11,44.98 87.89,46.2 74.3,46.2 72.72,44.62 U29.4
HUB1_G1: length 26.6
  TOP w0.152: P1.P1 98.3,41.05 U27.7 98.3,43.66 99.32,44.67 101.73,44.67 R159.1
HUB1_G2: length 28.6
  TOP w0.152: R162.1 107.45,43.02 103.51,46.96 98.68,46.96 96.35,44.63 U27.4 96.35,41.58 95,40.23 93.35,40.23 91.32,38.2 91.32,37.82 89.92,36.42 89.92,35.67 P1.R3
HUB1_LATCH: length 30.9
  TOP w0.152: P1.P9 83.87,34.63 83.87,36.47 84.89,37.49 84.89,38.25 87.81,41.17 U28.4 87.81,44.75 87.13,45.44 76.84,45.44 v1(76.46,45.05) ; v1(71.76,44.29) 71.42,43.96 U29.2
  BOTTOM w0.152: v1(71.76,44.29) 75.7,44.29 v1(76.46,45.05)
HUB1_OE: length 29.4
  TOP w0.152: U29.3 72.07,41.57 73.03,40.61 76.59,40.61 77.47,41.5 77.47,44.42 77.73,44.67 86.11,44.67 86.51,44.27 U28.2 86.51,41.26 82.43,37.18 82.43,37.05 82.41,37.04 P1.T10
HUB1_R1: length 25.1
  TOP w0.152: P1.R1 97.65,41.4 U27.6 97.65,43.77 99.06,45.18 103.26,45.18 107.7,40.74 R158.1
HUB1_R2: length 27.4
  TOP w0.152: P1.T3 89.41,36.55 90.62,37.76 90.62,38.26 93.1,40.74 94.75,40.74 95.7,41.69 U27.3 95.7,44.61 98.43,47.34 104.14,47.34 106.18,45.31 R161.1
HUB2_B1: length 6.9
  TOP w0.152: P1.T12 80.27,36.3 80.27,40.48 80.74,40.95 U30.5
HUB2_B2: length 7.9
  TOP w0.152: P1.R11 81.92,35.67 81.92,37.18 82.04,37.3 U30.7
HUB2_BUF_A: length 28.1
  TOP w0.152: U29.12 75.97,50.06 73.23,52.8 57.15,52.8 56.52,53.44 56.52,54.83 55.88,55.47 54.03,55.47 J11.9
HUB2_BUF_B: length 24.9
  TOP w0.152: U29.14 74.67,49.96 72.85,51.79 55.17,51.79 J11.10
HUB2_BUF_B1: length 26
  TOP w0.152: J11.3 61.59,58.01 64.39,58.01 65.03,57.37 73.88,57.37 81.39,49.85 U30.15
HUB2_BUF_B2: length 33.4
  TOP w0.152: U30.13 82.69,49.95 74.26,58.38 66.05,58.38 65.28,59.15 57.65,59.15 J11.7
HUB2_BUF_C: length 29.9
  TOP w0.152: U29.13 75.32,50.08 73.11,52.29 55.38,52.29 53.98,53.69 53.98,54.83 53.34,55.47 51.49,55.47 J11.11
HUB2_BUF_CLK: length 30.9
  TOP w0.152: J11.13 48.82,55.6 50.42,55.6 51.44,54.58 51.44,53.82 53.85,51.4 72.72,51.4 74.02,50.11 U29.15
HUB2_BUF_D: length 26.2
  TOP w0.152: J11.12 53.52,50.9 72.47,50.9 73.37,50 U29.16
HUB2_BUF_G1: length 19.3
  TOP w0.152: U30.18 79.44,49.64 74.85,54.23 J11.2
HUB2_BUF_G2: length 26.1
  TOP w0.152: J11.6 59.05,55.47 74.38,55.47 80.09,49.76 U30.17
HUB2_BUF_LATCH: length 27.3
  TOP w0.152: J11.14 52,49.88 71.96,49.88 72.07,49.77 U29.18
HUB2_BUF_OE: length 32.2
  TOP w0.152: J11.15 46.41,55.47 48.26,55.47 49.03,54.71 49.03,53.69 52.33,50.39 72.22,50.39 72.72,49.88 U29.17
HUB2_BUF_R1: length 21.8
  TOP w0.152: U30.16 80.74,49.87 73.84,56.77 J11.1
HUB2_BUF_R2: length 29.8
  TOP w0.152: U30.14 82.04,49.96 74.09,57.91 65.66,57.91 64.93,58.64 59.68,58.64 J11.5
HUB2_G1: length 7.9
  TOP w0.152: U30.2 78.79,41.24 78.89,41.15 78.89,35.68 P1.R13
HUB2_G2: length 6.7
  TOP w0.152: U30.3 79.44,41.29 79.27,41.12 79.27,36.3 P1.T13
HUB2_R1: length 7.9
  TOP w0.152: U30.4 80.09,40.99 79.89,40.79 79.89,35.68 P1.R12
HUB2_R2: length 6.8
  TOP w0.152: P1.T11 81.41,37.05 81.41,37.05 81.41,37.31 81.67,37.56 81.67,40.86 81.39,41.14 U30.6
HUB3_A: length 33.1
  TOP w0.152: P1.D11 v1(80.91,23.66)
  BOTTOM w0.152: v1(80.91,23.66) 80.91,23.47 80.41,22.97 80.41,21.31 80.16,21.05 77.55,21.05 76.71,20.21 76.71,18.78 75.17,17.24 74.55,17.24 73.76,16.45 U31.8 73.76,14.1 74.05,13.81 80.78,13.81 81.41,13.18 89.31,13.18 89.77,13.64 U33.2
HUB3_B: length 36.5
  TOP w0.152: P1.E10 v1(81.91,24.66)
  BOTTOM w0.152: v1(81.91,24.66) 81.62,24.66 81.12,24.16 80.7,24.16 80.41,23.87 80.41,23.46 80.12,23.16 78.57,23.16 77.73,22.32 76.54,22.32 73.11,18.89 U31.7 73.11,14.12 73.79,13.43 80.52,13.43 81.16,12.8 89.54,12.8 90.42,13.68 U33.3
HUB3_B1: length 38.9
  TOP w0.152: v1(80.91,31.66) 81.41,31.16 P1.L11
  BOTTOM w0.152: v1(80.91,31.66) 80.41,32.16 79.7,32.16 79.41,32.46 79.41,32.87 79.04,33.24 78.62,33.24 78.52,33.15 77.47,33.15 77.12,33.5 72.24,33.5 72.07,33.32 71.56,33.32 70.36,34.52 70.35,34.52 64.49,34.52 63.04,33.06 U32.4
HUB3_B2: length 36.5
  TOP w0.152: P1.L13 v1(79.91,31.66)
  BOTTOM w0.152: v1(79.91,31.66) 79.62,31.66 79.12,32.16 78.63,32.16 78.05,32.74 73.68,32.74 73.49,32.93 73.28,33.14 72.39,33.14 72.15,32.9 71.47,32.9 70.21,34.16 65.06,34.16 63.69,32.79 U32.5
HUB3_BUF_A: length 26
  BOTTOM w0.152: U31.12 74.41,4.78 71.25,1.62 66.09,1.62 65.31,0.83 57.67,0.83 J13.9
HUB3_BUF_B: length 27
  BOTTOM w0.152: J13.10 56.65,4.39 56.65,2.51 57.87,1.29 64.82,1.29 65.81,2.27 70.98,2.27 73.76,5.05 U31.13
HUB3_BUF_B1: length 23.1
  BOTTOM w0.152: J13.3 48.74,4.32 48.74,7.31 52.84,11.4 62.87,11.4 63.69,10.58 U32.16
HUB3_BUF_B2: length 16.2
  BOTTOM w0.152: J13.7 53.85,4.35 53.85,6.57 54.51,7.23 64.01,7.23 64.34,7.56 U32.15
HUB3_BUF_C: length 21.1
  BOTTOM w0.152: U31.14 73.11,5.32 70.71,2.92 65.57,2.92 64.37,1.72 59.32,1.72 J13.11
HUB3_BUF_CLK: length 16.7
  BOTTOM w0.152: U31.16 71.81,5.85 70.17,4.22 65.72,4.22 63.61,2.1 61.48,2.1 J13.13
HUB3_BUF_D: length 18.2
  BOTTOM w0.152: J13.12 58.92,6.88 66.62,6.88 67.7,7.95 67.7,9.37 68.46,10.13 72.14,10.13 72.46,9.81 U31.15
HUB3_BUF_G1: length 25.4
  BOTTOM w0.152: J13.2 51.5,12.16 64.04,12.16 65.64,10.57 U32.13
HUB3_BUF_G2: length 14.2
  BOTTOM w0.152: U32.18 62.39,7.9 62.11,7.62 52.04,7.62 J13.6
HUB3_BUF_LATCH: length 14.3
  BOTTOM w0.152: J13.14 61.58,4.54 64.14,4.54 65.12,5.52 69.64,5.52 70.74,6.63 70.74,7.99 70.51,8.22 U31.18
HUB3_BUF_OE: length 12.4
  BOTTOM w0.152: J13.15 64.1,3.23 65.74,4.87 69.9,4.87 71.16,6.12 U31.17
HUB3_BUF_R1: length 26.5
  BOTTOM w0.152: U32.14 64.99,10.68 63.89,11.78 51.95,11.78 46.36,6.19 46.36,4.48 J13.1
HUB3_BUF_R2: length 21.2
  BOTTOM w0.152: J13.5 49.1,4.32 49.1,6.52 53.6,11.02 62.49,11.02 63.04,10.47 U32.17
HUB3_C: length 35.1
  TOP w0.152: P1.D14 v1(78.91,23.66)
  BOTTOM w0.152: U33.4 91.07,13.69 89.79,12.42 81.03,12.42 80.4,13.05 73.54,13.05 72.46,14.13 U31.6 72.46,18.96 76.33,22.83 77.78,22.83 78.62,23.66 v1(78.91,23.66)
HUB3_CLK: length 42.8
  TOP w0.152: P1.D12 v1(80.91,24.66)
  BOTTOM w0.152: v1(80.91,24.66) 80.62,24.66 80.12,24.16 77.54,24.16 77.22,23.85 75.7,23.85 71.16,19.31 U31.4 71.16,14.03 72.9,12.29 79.89,12.29 80.52,11.65 91.06,11.65 92.37,12.96 U33.6
HUB3_D: length 36.7
  TOP w0.152: P1.D15 v1(77.91,23.66)
  BOTTOM w0.152: U33.5 91.72,13.33 90.43,12.03 80.65,12.03 80.01,12.67 73.16,12.67 71.81,14.02 U31.5 71.81,19.07 76.08,23.34 77.58,23.34 v1(77.91,23.66)
HUB3_G1: length 25.5
  TOP w0.152: v1(80.91,26.66) P1.G11 ; v1(70.36,22.83) 69.56,22.03 v1(64.99,22.03)
  BOTTOM w0.152: v1(64.99,22.03) U32.7 ; v1(80.91,26.66) 80.62,26.66 80.12,26.16 73.7,26.16 v1(70.36,22.83)
HUB3_G2: length 39.8
  TOP w0.152: v1(80.91,33.66) 81.41,33.16 P1.N11
  BOTTOM w0.152: U32.2 61.74,33.6 63.39,35.25 72.55,35.25 73.03,34.77 77.98,34.77 78.59,34.16 80.41,34.16 v1(80.91,33.66)
HUB3_LATCH: length 47.1
  TOP w0.152: P1.F13 v1(78.91,25.66)
  BOTTOM w0.152: v1(78.91,25.66) 74.21,25.66 69.86,21.31 U31.2 69.86,13.56 71.89,11.53 79.38,11.53 80.01,10.89 91.57,10.89 93.67,12.99 U33.8
HUB3_OE: length 46.6
  TOP w0.152: P1.E11 v1(80.91,25.66)
  BOTTOM w0.152: U33.7 93.02,12.98 91.32,11.27 80.24,11.27 79.6,11.91 72.52,11.91 70.51,13.92 U31.3 70.51,21.2 74.47,25.16 80.44,25.16 80.91,25.63 v1(80.91,25.66)
HUB3_R1: length 24.9
  TOP w0.152: v1(65.16,26) 65.71,26.56 68.63,26.56 69.5,27.43 74.2,27.43 75.44,28.67 76.92,28.67 P1.J15
  BOTTOM w0.152: v1(65.16,26) 64.34,25.19 U32.6
HUB3_R2: length 39.1
  TOP w0.152: v1(80.91,32.66) 81.41,32.16 P1.M11
  BOTTOM w0.152: U32.3 62.39,33.33 63.95,34.89 72.01,34.89 72.58,34.32 77.98,34.32 78.68,33.62 79.13,33.62 79.59,33.16 80.41,33.16 v1(80.91,32.66)
HUB4_B1: length 10.1
  TOP w0.152: P1.D9 v1(82.91,23.66)
  BOTTOM w0.152: v1(82.91,23.66) 82.41,23.16 82.41,22.34 83.7,21.05 83.7,16.1 83.58,15.98 U34.4
HUB4_B2: length 16
  TOP w0.152: v1(85.34,16.89) 85.15,17.08 85.15,17.59 84.45,18.29 84.45,20.32 83.91,20.87 83.91,29.66 P1.K9
  BOTTOM w0.152: U34.7 85.53,15.75 85.34,15.93 v1(85.34,16.89)
HUB4_BUF_A: length 8.7
  BOTTOM w0.152: U33.18 90.42,7.85 91.64,6.63 91.64,5.32 92.41,4.54 93.96,4.54 J12.9
HUB4_BUF_B: length 6.2
  BOTTOM w0.152: J12.10 94.15,6.89 92.09,6.89 91.07,7.9 U33.17
HUB4_BUF_B1: length 7.5
  BOTTOM w0.152: J12.3 86.36,4.52 86.36,6.32 85.73,6.95 85.22,6.95 84.23,7.95 U34.16
HUB4_BUF_B2: length 11.9
  BOTTOM w0.152: U34.13 86.18,9.94 86.31,10.08 87.77,10.08 88.27,9.58 88.27,8.55 89.48,7.34 90.17,7.34 91.28,6.22 91.28,4.68 J12.7
HUB4_BUF_C: length 10.2
  BOTTOM w0.152: J12.11 96.52,4.52 96.52,6.32 95.58,7.26 92.41,7.26 91.72,7.95 U33.16
HUB4_BUF_CLK: length 11.3
  BOTTOM w0.152: J12.13 99.06,4.52 99.06,6.19 97.29,7.97 93.15,7.97 93.02,8.1 U33.14
HUB4_BUF_D: length 7.4
  BOTTOM w0.152: U33.15 92.37,7.93 92.69,7.62 95.96,7.62 J12.12
HUB4_BUF_G1: length 3.9
  BOTTOM w0.152: J12.2 83.58,7.3 U34.17
HUB4_BUF_G2: length 6.6
  BOTTOM w0.152: U34.14 85.53,8.12 85.86,7.79 88.17,7.79 J12.6
HUB4_BUF_LATCH: length 8.9
  BOTTOM w0.152: J12.14 95.86,10.26 94.75,10.26 94.32,9.83 U33.12
HUB4_BUF_OE: length 14.5
  BOTTOM w0.152: J12.15 101.6,4.52 101.6,6.32 97.29,10.64 94.37,10.64 93.67,9.94 U33.13
HUB4_BUF_R1: length 6.7
  BOTTOM w0.152: U34.18 82.93,5.41 J12.1
HUB4_BUF_R2: length 9.3
  BOTTOM w0.152: U34.15 84.88,8.19 85.73,7.34 87.89,7.34 88.9,6.32 88.9,4.52 J12.5
HUB4_G1: length 13.1
  TOP w0.152: P1.F9 v1(82.91,25.66)
  BOTTOM w0.152: U34.3 82.93,15.85 82.17,16.61 81.79,16.61 81.41,16.99 81.41,23.87 81.7,24.16 82.12,24.16 82.41,24.46 82.41,25.16 v1(82.91,25.66)
HUB4_G2: length 11.2
  TOP w0.152: P1.E9 v1(82.91,24.66)
  BOTTOM w0.152: v1(82.91,24.66) 82.91,24.63 83.7,23.85 83.7,22.58 84.71,21.56 84.71,16.13 84.88,15.96 U34.6
HUB4_R1: length 8.5
  TOP w0.152: P1.A14 77.86,20.61 v1(77.86,19.91)
  BOTTOM w0.152: v1(77.86,19.91) 77.86,19.65 81.41,16.1 81.92,16.1 82.28,15.74 U34.2
HUB4_R2: length 8.9
  TOP w0.152: P1.C9 v1(82.91,22.66)
  BOTTOM w0.152: U34.5 84.23,21.34 v1(82.91,22.66)
MIIA_GTX_CLK: length 6
  TOP w0.152: R39.2 54.14,35.66 53.88,35.66 53.5,36.04 51.73,36.04 50.69,37.07 U8.33
MIIA_RX_CLK: length 7.2
  TOP w0.152: U8.31 50.22,36.27 51.73,34.77 53.38,34.77 54.01,34.13 R121.2 R91.2
MIIA_RX_D0: length 9.7
  TOP w0.152: U8.29 48.05,34.64 49.31,33.37 49.82,33.37 50.84,32.35 53.13,32.35 54.02,31.47 R27.2 R95.2
MIIA_RX_D1: length 7.8
  TOP w0.152: U8.28 47.65,34.4 49.06,32.99 49.57,32.99 51.09,31.47 R99.2 R30.2
MIIA_RX_D2: length 6.3
  TOP w0.152: R35.2 49.06,31.72 R105.2 R103.2 47.15,32.17 46.84,32.48 U8.26
MIIA_RX_D3: length 3.1
  TOP w0.152: R37.2 R96.2 46.45,34.19 U8.25
MIIA_RX_DV: length 6.1
  TOP w0.152: U8.30 48.45,34.75 49.46,33.73 50.81,33.73 51.22,34.13 R107.2 R24.2
MIIA_TX_D0: length 3.4
  TOP w0.152: U8.34 50.8,37.47 51.6,36.67 R43.2
MIIA_TX_D1: length 5.8
  TOP w0.152: R45.2 54.14,36.93 53.88,36.93 53.5,37.31 51.6,37.31 51.04,37.87 U8.35
MIIA_TX_D2: length 3.2
  TOP w0.152: U8.36 51.78,38.27 R47.2
MIIA_TX_D3: length 5.6
  TOP w0.152: R49.2 53.67,38.67 U8.37
MIIA_TX_EN: length 3.6
  TOP w0.152: R41.2 51.73,35.4 50.46,36.67 U8.32
MIIB_GTX_CLK: length 2.8
  TOP w0.152: R40.2 51.22,18.89 50.57,19.54 U9.33
MIIB_RX_CLK: length 7.4
  TOP w0.152: R93.2 R22.2 54.73,17.88 50.96,17.88 50.1,18.74 U9.31
MIIB_RX_D0: length 9.8
  TOP w0.152: R97.2 R28.2 54.77,15.46 51.09,15.46 50.9,15.65 49.5,15.65 48.05,17.11 U9.29
MIIB_RX_D1: length 7.2
  TOP w0.152: U9.28 47.65,16.88 49.31,15.21 50.58,15.21 50.96,14.83 R101.2 R32.2
MIIB_RX_D2: length 6.3
  TOP w0.152: U9.26 46.84,14.96 47.15,14.65 R104.2 R106.2 49.06,14.19 R36.2
MIIB_RX_D3: length 3.1
  TOP w0.152: U9.25 46.45,16.66 R98.2 R38.2
MIIB_RX_DV: length 5.7
  TOP w0.152: R108.2 R25.2 49.57,16.1 48.45,17.22 U9.30
MIIB_TX_D0: length 6.2
  TOP w0.152: U9.34 50.67,19.94 51.09,19.53 53.76,19.53 54.27,20.04 R44.2
MIIB_TX_D1: length 2.6
  TOP w0.152: R46.2 51.42,20.34 U9.35
MIIB_TX_D2: length 6.1
  TOP w0.152: R48.2 54.29,21.33 53.7,20.74 U9.36
MIIB_TX_D3: length 6.7
  TOP w0.152: R50.2 54.01,21.84 54.01,21.56 53.6,21.14 U9.37
MIIB_TX_EN: length 6.4
  TOP w0.152: R42.2 54.11,18.81 53.6,18.3 51.17,18.3 50.33,19.14 U9.32
NCONFIG: length 3.9
  TOP w0.152: P1.H5 v1(87.91,27.66)
  BOTTOM w0.152: R17.1 88.28,28.04 v1(87.91,27.66)
NCSO: length 25.7
  TOP w0.152: P1.D2 90.89,24.64 94.46,24.64 95.25,23.85 98.68,23.85 99.7,24.86 99.7,28.93 100.72,29.94 100.72,31.62 v1(100.46,31.87) ; U7.1 101.85,36.93 102.24,36.55 v1(102.24,34.26)
  BOTTOM w0.152: v1(100.46,31.87) 100.46,31.88 101.22,32.64 102.29,32.64 102.49,32.84 102.49,34.06 102.29,34.26 v1(102.24,34.26)
NRST: length 3.5
  TOP w0.152: U26.14 108.85,31.94 R5.2 C11.2
NSTATUS: length 1.6
  TOP w0.152: P1.F4 v1(88.91,26.66)
  BOTTOM w0.152: v1(88.91,26.66) 88.74,26.83 R16.1
P0MDIA+: length 8.4
  TOP w0.254: J2.1 16.4,41.51 17.19,42.29 18.63,42.29 19.9,41.02 21.11,41.02 21.34,41.24 U23.25
P0MDIA-: length 7.8
  TOP w0.254: U23.26 21.46,40.23 21.18,40.51 19.68,40.51 18.41,41.78 17.4,41.78 17.02,41.4 17.02,40.91 J2.2
P0MDIB+: length 8
  TOP w0.254: U23.28 21.15,38.2 v1(21.14,38.21)
  BOTTOM w0.254: v1(21.14,38.21) 20.87,37.95 19.08,37.95 18.06,38.97 J2.3
P0MDIB-: length 6.5
  TOP w0.254: v1(21.14,37.17) 21.15,37.18 U23.29
  BOTTOM w0.254: v1(21.14,37.17) 20.86,37.44 19.02,37.44 17.69,36.11 J2.6
P0MDIC+: length 6.3
  TOP w0.254: U23.31 21.34,35.15 21.11,34.92 20.66,34.92 20.45,35.14 20.45,35.52 19.26,36.7 18.68,36.7 J2.4
P0MDIC-: length 8.6
  TOP w0.254: J2.5 18.29,36.43 18.52,36.2 19.05,36.2 19.94,35.31 19.94,34.92 20.45,34.42 21.18,34.42 21.46,34.13 U23.32
P0MDID+: length 8.9
  TOP w0.254: J2.7 17.78,33.89 17.93,34.04 18.75,34.04 19.68,33.1 19.68,32.47 20.4,31.75 21.08,31.75 21.43,32.1 U23.34
P0MDID-: length 6.9
  TOP w0.254: U23.35 21.24,31.08 21.08,31.24 20.19,31.24 19.18,32.26 19.18,32.89 18.54,33.53 18.16,33.53 17.69,33.06 J2.8
P1MDIA+: length 8.1
  TOP w0.254: J2.9 16.4,27.54 17.19,28.32 19.73,28.32 20.24,28.83 21.11,28.83 21.34,29.05 U23.37
P1MDIA-: length 7.5
  TOP w0.254: U23.38 21.46,28.04 21.18,28.32 20.45,28.32 19.94,27.81 17.4,27.81 17.02,27.43 17.02,26.94 J2.10
P1MDIB+: length 7.9
  TOP w0.254: U23.40 21.15,26 v1(21.14,26.02)
  BOTTOM w0.254: v1(21.14,26.02) 20.87,25.76 19.64,25.76 18.88,25 J2.11
P1MDIB-: length 7.8
  TOP w0.254: v1(21.14,24.98) 21.15,24.99 U23.41
  BOTTOM w0.254: v1(21.14,24.98) 20.86,25.25 19.86,25.25 19.02,24.41 19.02,23.47 17.69,22.14 J2.14
P1MDIC+: length 5.4
  TOP w0.254: U23.43 21.34,22.96 21.11,22.73 18.68,22.73 J2.12
P1MDIC-: length 7.6
  TOP w0.254: U23.44 21.46,21.94 21.18,22.23 18.52,22.23 18.29,22.46 J2.13
P1MDID+: length 7.8
  TOP w0.254: J2.15 17.78,19.92 17.93,20.07 19.26,20.07 19.77,19.56 21.08,19.56 21.43,19.91 U23.46
P1MDID-: length 5.8
  TOP w0.254: U23.47 21.24,18.89 21.08,19.05 19.56,19.05 19.05,19.56 18.16,19.56 17.69,19.09 J2.16
PHYA-GREEN: length 39.7
  TOP w0.152: v1(39.25,30.07) 39.48,30.3 R56.2 ; D37.2 17.15,47.59 17.91,46.83 26.96,46.83 27.85,45.94 v1(33.02,45.94)
  BOTTOM w0.152: v1(39.25,30.07) 38.77,30.54 38.77,39.09 37.09,40.77 37.09,44.17 35.95,45.31 33.66,45.31 v1(33.02,45.94)
PHYA-YELLOW: length 42.9
  TOP w0.152: D36.2 13.97,47.59 15.12,46.45 26.8,46.45 27.94,45.31 33.91,45.31 v1(34.55,45.94) ; v1(39.37,31.08) 39.79,31.08 41.18,32.48 R51.2
  BOTTOM w0.152: v1(34.55,45.94) 36.07,45.94 37.47,44.55 37.47,40.9 39.28,39.09 39.28,31.18 v1(39.37,31.08)
PHYB-GREEN: length 30.3
  TOP w0.152: R60.2 40.07,11.94 26.58,11.94 24.77,10.13 14.47,10.13 D35.2
PHYB-YELLOW: length 23.3
  TOP w0.152: D34.2 24.64,11.15 26.07,12.57 38.04,12.57 R52.2
RD: length 36.3
  TOP w0.152: v1(104.27,18.51) 104.83,19.07 113.34,19.07 114.45,20.19 U26.85 ; P1.D6 v1(86.91,23.66)
  BOTTOM w0.152: v1(104.27,18.51) 88.4,18.51 86.41,20.5 86.41,23.16 v1(86.91,23.66)
RS485_DE: length 97.3
  TOP w0.152: J6.8 24,4.75 30.65,11.4 58.17,11.4 59.44,12.67 82.55,12.67 87.25,7.97 104.4,7.97 v1(105.29,7.08) ; U26.52 v1(103.85,12.67)
  BOTTOM w0.152: v1(105.29,7.08) 105.29,11.23 v1(103.85,12.67)
RS485_RE: length 98.3
  TOP w0.152: v1(102.87,12.67) 103.35,13.15 U26.51 ; v1(29.08,2.41) 28.45,3.05 28.45,3.94 31.59,7.08 65.03,7.08 65.54,6.57 77.47,6.57 77.98,7.08 103.76,7.08 v1(105.29,5.56)
  BOTTOM w0.152: J6.7 23.17,2.92 28.57,2.92 v1(29.08,2.41) ; v1(102.87,12.67) 104.4,11.15 104.4,6.45 v1(105.29,5.56)
RS485_RX: length 102.3
  TOP w0.152: v1(106.56,5.56) 105.54,4.54 30.07,4.54 v1(29.08,3.56) ; U26.48 103.3,16.69 v1(103.89,16.1)
  BOTTOM w0.152: J6.6 21.81,3.56 v1(29.08,3.56) ; v1(106.56,5.56) 105.92,6.19 105.92,14.07 v1(103.89,16.1)
RS485_TX: length 99.3
  TOP w0.152: v1(104.91,16.1) 103.82,17.19 U26.47 ; J6.9 26,4.75 28.84,7.59 66.68,7.59 67.19,7.08 73.79,7.08 74.17,7.46 104.02,7.46 105.1,6.38 105.86,6.38 v1(106.56,7.08)
  BOTTOM w0.152: v1(106.56,7.08) 106.56,14.45 v1(104.91,16.1)
SD_A0: length 30.6
  TOP w0.152: P1.F1 93.6,26.16 93.98,26.54 93.98,28.14 95.25,29.41 95.25,30.4 95.45,30.61 95.63,30.61 95.81,30.43 95.81,29.9 95.99,29.72 96.24,29.72 96.42,29.9 96.42,31.32 96.6,31.5 96.85,31.5 97.03,31.32 97.03,29.9 97.21,29.72 97.46,29.72 97.64,29.9 97.64,30.66 97.84,30.86 98.86,30.86 99.06,30.66 v1(99.06,30.32)
  BOTTOM w0.152: U5.23 103.93,34.89 104.02,34.8 105.97,34.8 106.17,34.59 106.17,34.37 105.97,34.16 103.63,34.16 103.25,33.78 103.25,30.53 103.05,30.32 v1(99.06,30.32)
SD_A1: length 30.6
  TOP w0.152: P1.G2 90.93,26.64 93.22,26.64 93.58,27 93.58,28.56 v4(93.73,28.7) 94.01,28.7 94.81,29.5 94.81,30.55 95.25,30.99 95.25,32.47 95.42,32.64 95.66,32.64 95.83,32.47 95.83,31.93 96.01,31.75 96.26,31.75 96.44,31.93 96.44,32.46 96.62,32.64 96.87,32.64 97.05,32.46 97.05,31.93 97.23,31.75 97.48,31.75 97.66,31.93 97.66,32.44 97.86,32.64 98.23,32.64 98.43,32.44 v1(98.43,31.47)
  BOTTOM w0.152: v1(98.43,31.47) 98.43,31.19 98.63,30.99 99.19,30.99 99.31,30.86 99.78,30.86 99.9,30.73 100.25,30.73 100.43,30.91 100.43,31.06 100.61,31.24 100.86,31.24 101.04,31.06 101.04,30.91 101.22,30.73 101.4,30.73 101.6,30.94 101.6,32.05 101.8,32.26 102.03,32.26 102.23,32.05 102.23,30.94 102.44,30.73 102.67,30.73 102.87,30.94 102.87,34.04 103.06,34.22 103.17,34.22 103.38,34.43 103.38,34.68 103.13,34.92 U5.24
SD_A2: length 31
  TOP w0.152: v1(103.26,37.82) 103.26,38.32 103.12,38.45 102.78,38.45 102.6,38.27 102.6,37.77 102.42,37.59 102.17,37.59 101.99,37.77 101.99,38.27 101.81,38.45 101.56,38.45 101.38,38.27 101.38,37.77 101.2,37.59 100.95,37.59 100.77,37.77 100.77,38.27 100.59,38.45 100.34,38.45 100.16,38.27 100.16,37.77 99.98,37.59 99.73,37.59 99.55,37.77 99.55,38.27 99.37,38.45 99.12,38.45 98.94,38.27 98.94,36.63 98.76,36.45 98.51,36.45 98.33,36.63 98.33,38.27 98.15,38.45 97.41,38.45 96.98,38.02 96.98,37.77 97.41,37.34 97.41,37.09 97.23,36.91 96.98,36.91 96.55,37.34 96.3,37.34 96.12,37.16 96.12,36.91 96.55,36.48 96.55,36.22 96.37,36.05 96.12,36.05 95.69,36.47 95.44,36.47 93.98,35.02 93.98,31.34 91.81,29.16 P1.J1
  BOTTOM w0.152: v1(103.26,37.82) 102.33,36.89 U5.25
SD_A3: length 30.4
  TOP w0.152: P1.G1 91.55,27.02 92.71,27.02 92.96,27.27 92.96,28.7 94.03,29.76 v1(94.24,29.76)
  BOTTOM w0.152: v1(94.24,29.76) 94.24,28.36 94.4,28.19 94.63,28.19 94.8,28.36 94.8,29.67 94.97,29.84 95.23,29.84 95.41,29.67 95.41,28.63 95.58,28.45 95.74,28.45 95.94,28.65 95.94,30.03 96.12,30.2 96.36,30.2 97.13,29.44 97.38,29.44 97.56,29.62 97.56,29.87 96.77,30.66 96.77,30.87 96.92,31.01 97.13,31.01 97.28,30.87 97.28,30.87 97.86,30.29 98.11,30.29 98.29,30.47 98.29,30.72 97.72,31.3 97.72,31.55 98.78,32.61 99.05,32.61 99.23,32.43 99.23,31.55 99.41,31.37 99.66,31.37 99.84,31.55 99.84,32.43 100.02,32.61 100.59,32.61 100.84,32.86 100.84,32.99 101.02,33.17 101.93,33.17 102.11,33.35 102.11,33.6 101.93,33.78 101.02,33.78 100.84,33.96 100.84,34.29 101.53,34.98 U5.26
SD_A4: length 30.2
  TOP w0.152: P1.N5 v1(87.91,33.66)
  BOTTOM w0.152: v1(87.91,33.66) 87.91,33.9 88.41,34.4 88.41,37.61 88.89,38.09 88.89,38.35 88.51,38.73 88.51,38.98 88.69,39.16 88.94,39.16 89.33,38.78 89.58,38.78 89.76,38.96 89.76,39.21 89.37,39.59 89.37,39.84 89.55,40.02 89.81,40.02 90.19,39.64 90.44,39.64 90.62,39.82 90.62,40.07 90.24,40.45 90.24,40.71 90.42,40.89 90.67,40.89 91.05,40.5 91.3,40.5 91.48,40.68 91.48,40.93 91.1,41.32 91.1,41.57 91.28,41.75 91.53,41.75 91.91,41.37 92.17,41.37 92.33,41.53 92.33,44.67 93.1,45.44 101.1,45.44 101.53,45.87 U5.29
SD_A5: length 30.3
  TOP w0.152: P1.T5 v1(87.91,36.66)
  BOTTOM w0.152: v1(87.91,36.66) 87.91,39.01 91.06,42.16 91.06,42.7 91.24,42.88 91.77,42.88 91.95,43.06 91.95,43.31 91.77,43.49 91.24,43.49 91.06,43.67 91.06,45.3 91.46,45.71 91.72,45.71 92.15,45.28 92.4,45.28 92.58,45.46 92.58,45.71 92.15,46.14 92.15,46.39 92.33,46.57 92.58,46.57 92.94,46.21 93.2,46.21 93.38,46.39 93.38,46.64 93.01,47 93.01,47.26 93.89,48.13 94.91,48.13 95.17,48.39 95.63,48.39 95.89,48.13 95.9,48.13 96.08,47.95 96.08,47.8 96.26,47.62 96.51,47.62 96.69,47.8 96.69,47.95 96.87,48.13 97.16,48.13 97.92,47.37 99.95,47.37 100.15,47.58 100.15,48.18 100.46,48.48 102.11,48.48 102.33,48.26 U5.30
SD_A6: length 30.2
  TOP w0.152: P1.R5 v1(87.91,35.66)
  BOTTOM w0.152: v1(87.91,35.66) 87.88,35.66 87.38,36.16 87.38,40.86 90.62,44.1 90.62,45.37 94.11,48.86 97.65,48.86 97.83,48.69 97.83,48.18 98.01,48.01 98.26,48.01 98.44,48.18 98.44,48.69 98.62,48.86 98.87,48.86 99.05,48.69 99.05,47.93 99.23,47.75 99.48,47.75 99.66,47.93 99.66,48.69 99.84,48.86 102.49,48.86 103.13,48.23 U5.31
SD_A7: length 31
  TOP w0.152: P1.N6 v1(86.91,33.66)
  BOTTOM w0.152: U5.32 103.93,48.31 102.99,49.26 94,49.26 90.18,45.44 90.18,44.3 86.87,40.99 86.87,35.78 87.41,35.25 87.41,34.16 v1(86.91,33.66)
SD_A8: length 31.5
  TOP w0.152: P1.P6 v1(86.91,34.66)
  BOTTOM w0.152: v1(86.91,34.66) 86.91,35.11 86.36,35.66 86.36,41.12 89.54,44.29 89.54,45.31 93.86,49.63 103.51,49.63 104.73,48.4 U5.33
SD_A9: length 35.2
  TOP w0.152: P1.M7 v1(85.91,32.66)
  BOTTOM w0.152: v1(85.91,32.66) 85.41,33.16 85.41,34.92 85.93,35.45 85.93,41.32 88.84,44.23 88.84,45.12 93.73,50.01 103.89,50.01 105.53,48.37 U5.34
SD_A10: length 30.5
  TOP w0.152: v1(104.14,37.82) 104.14,38.7 103.89,38.96 103.66,38.96 103.48,39.14 103.48,40.21 103.3,40.39 103.05,40.39 102.87,40.21 102.87,39.14 102.69,38.96 102.44,38.96 102.26,39.14 102.26,40.21 102.08,40.39 101.83,40.39 101.65,40.21 101.65,39.14 101.47,38.96 101.22,38.96 101.04,39.14 101.04,40.21 100.86,40.39 100.61,40.39 100.43,40.21 100.43,39.14 100.25,38.96 97.03,38.96 93.48,35.4 93.48,31.34 91.83,29.69 90.93,29.69 P1.J2
  BOTTOM w0.152: U5.22 104.73,37.23 v1(104.14,37.82)
